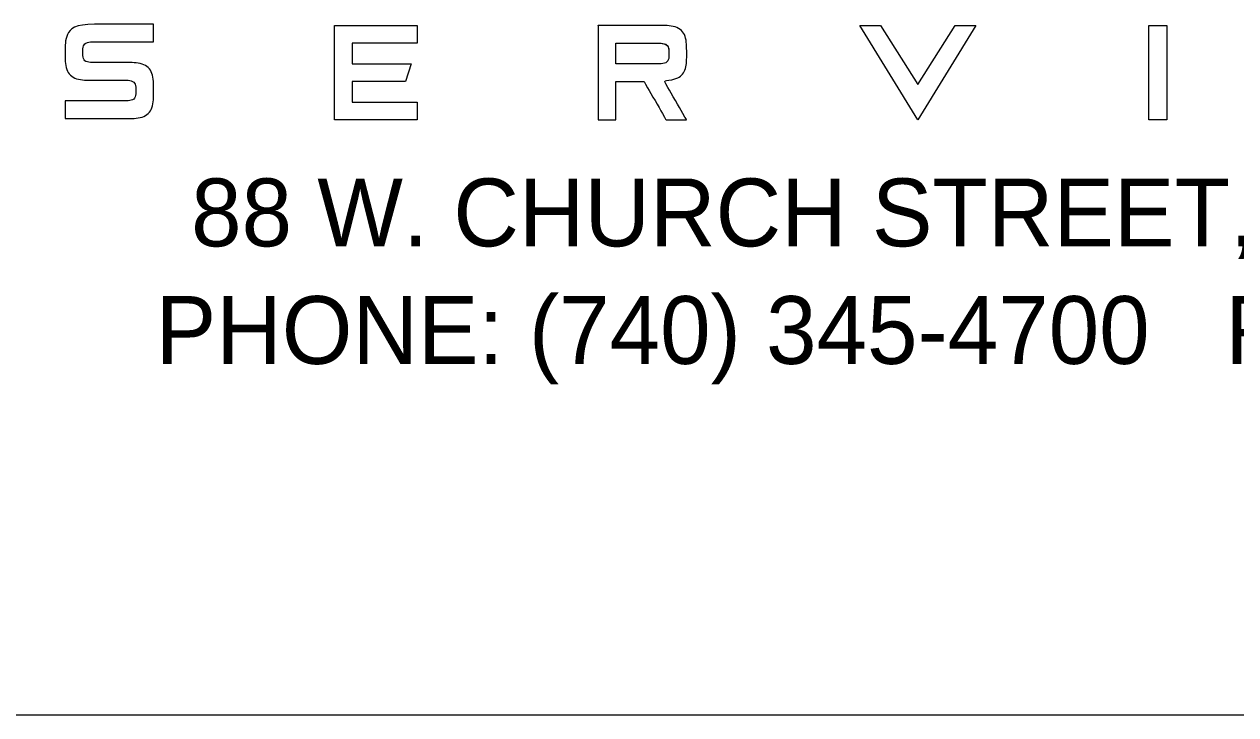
# Model space of a CAD drawing. Extents: x -50 to 112, y -27 to 22.
# Drawn here: x 71.03 to 71.911, y 2.5 to 3.003 of the extents above; entities that cross this region are included whole.
import ezdxf

# ---------------------------------------------------------------- set-up
doc = ezdxf.new("R2010")
doc.units = 0
doc.layers.add('Default', color=7, linetype='Continuous')
doc.layers.add('SH_Border', color=7, linetype='Continuous')

msp = doc.modelspace()

# ---------------------------------------------------------------- linework, layer by layer
at = {"layer": 'Default'}
for p, q in [((71.2555, 2.93307), (71.2555, 3.00176)), ((71.2555, 3.00176), (71.3156, 3.00176)), ((71.3156, 3.00176), (71.3156, 2.98888)), ((71.67986, 2.93307), (71.63775, 3.00176)), ((71.63775, 3.00176), (71.6526, 3.00176)), ((71.6526, 3.00176), (71.67986, 2.95883)), ((71.67986, 2.95883), (71.70713, 3.00176)), ((71.72198, 3.00176), (71.67986, 2.93307)), ((71.70713, 3.00176), (71.72198, 3.00176)), ((71.84804, 2.93307), (71.84804, 3.00176)), ((71.84804, 3.00176), (71.86092, 3.00176)), ((71.86092, 3.00176), (71.86092, 2.93307)), ((71.3156, 2.98888), (71.26838, 2.98888)), ((71.26838, 2.98888), (71.26838, 2.97385)), ((71.26838, 2.97385), (71.31131, 2.97385)), ((71.31131, 2.97385), (71.30702, 2.96097)), ((71.30702, 2.96097), (71.26838, 2.96097)), ((71.26838, 2.96097), (71.26838, 2.94595)), ((71.26838, 2.94595), (71.3156, 2.94595)), ((71.3156, 2.94595), (71.3156, 2.93307)), ((71.3156, 2.93307), (71.2555, 2.93307)), ((71.86092, 2.93307), (71.84804, 2.93307))]:
    msp.add_line(p, q, dxfattribs=at)
for points in [[(71.26838, 2.94595), (71.3156, 2.94595), (71.3156, 2.93307), (71.2555, 2.93307), (71.2555, 3.00176), (71.3156, 3.00176), (71.3156, 2.98888), (71.26838, 2.98888), (71.26838, 2.97385), (71.31131, 2.97385), (71.30702, 2.96097), (71.26838, 2.96097), (71.26838, 2.94595)], [(71.6526, 3.00176), (71.67986, 2.95883), (71.70713, 3.00176), (71.72198, 3.00176), (71.67986, 2.93307), (71.63775, 3.00176), (71.6526, 3.00176)], [(71.86092, 2.93307), (71.84804, 2.93307), (71.84804, 3.00176), (71.86092, 3.00176), (71.86092, 2.93307)]]:
    msp.add_lwpolyline(points, dxfattribs=at)
for points, degree in [([(71.08088, 3.00265), (71.08088, 3.00265), (71.12381, 3.00265), (71.12381, 3.00265), (71.12381, 3.00265), (71.12381, 2.98977), (71.12381, 2.98977), (71.12381, 2.98977), (71.08088, 2.98977), (71.08088, 2.98977), (71.07515, 2.98977), (71.07229, 2.98726), (71.07229, 2.98225), (71.07229, 2.97724), (71.07515, 2.97474), (71.08088, 2.97474), (71.08088, 2.97474), (71.10235, 2.97474), (71.10235, 2.97474), (71.11666, 2.97474), (71.12381, 2.96794), (71.12381, 2.95435), (71.12381, 2.94075), (71.11666, 2.93395), (71.10235, 2.93395), (71.10235, 2.93395), (71.05941, 2.93395), (71.05941, 2.93395), (71.05941, 2.93395), (71.05941, 2.94683), (71.05941, 2.94683), (71.05941, 2.94683), (71.10235, 2.94683), (71.10235, 2.94683), (71.10807, 2.94683), (71.11093, 2.94934), (71.11093, 2.95435), (71.11093, 2.95936), (71.10807, 2.96186), (71.10235, 2.96186), (71.10235, 2.96186), (71.08088, 2.96186), (71.08088, 2.96186), (71.06657, 2.96186), (71.05941, 2.96866), (71.05941, 2.98225), (71.05941, 2.99585), (71.06657, 3.00265), (71.08088, 3.00265)], 3), ([(71.08088, 3.00265), (71.08088, 3.00265), (71.12381, 3.00265), (71.12381, 3.00265), (71.12381, 3.00265), (71.12381, 2.98977), (71.12381, 2.98977), (71.12381, 2.98977), (71.08088, 2.98977), (71.08088, 2.98977), (71.07515, 2.98977), (71.07229, 2.98726), (71.07229, 2.98225), (71.07229, 2.97724), (71.07515, 2.97474), (71.08088, 2.97474), (71.08088, 2.97474), (71.10235, 2.97474), (71.10235, 2.97474), (71.11666, 2.97474), (71.12381, 2.96794), (71.12381, 2.95435), (71.12381, 2.94075), (71.11666, 2.93395), (71.10235, 2.93395), (71.10235, 2.93395), (71.05941, 2.93395), (71.05941, 2.93395), (71.05941, 2.93395), (71.05941, 2.94683), (71.05941, 2.94683), (71.05941, 2.94683), (71.10235, 2.94683), (71.10235, 2.94683), (71.10807, 2.94683), (71.11093, 2.94934), (71.11093, 2.95435), (71.11093, 2.95936), (71.10807, 2.96186), (71.10235, 2.96186), (71.10235, 2.96186), (71.08088, 2.96186), (71.08088, 2.96186), (71.06657, 2.96186), (71.05941, 2.96866), (71.05941, 2.98225), (71.05941, 2.99585), (71.06657, 3.00265), (71.08088, 3.00265)], 3), ([(71.44729, 3.00176), (71.44729, 3.00176), (71.44729, 2.93307), (71.44729, 2.93307)], 2), ([(71.44729, 2.93307), (71.44729, 2.93307), (71.46017, 2.93307), (71.46017, 2.93307), (71.46017, 2.93307), (71.46017, 2.96097), (71.46017, 2.96097), (71.46017, 2.96097), (71.4806, 2.96097), (71.4806, 2.96097), (71.4806, 2.96097), (71.4967, 2.93307), (71.4967, 2.93307), (71.4967, 2.93307), (71.5116, 2.93307), (71.5116, 2.93307), (71.5116, 2.93307), (71.49529, 2.96132), (71.49529, 2.96132), (71.50622, 2.9628), (71.51169, 2.96949), (71.51169, 2.98137), (71.51169, 2.99496), (71.50453, 3.00176), (71.49022, 3.00176), (71.49022, 3.00176), (71.44729, 3.00176), (71.44729, 3.00176)], 3), ([(71.44729, 3.00176), (71.44729, 3.00176), (71.49022, 3.00176), (71.49022, 3.00176), (71.50453, 3.00176), (71.51169, 2.99496), (71.51169, 2.98137), (71.51169, 2.96949), (71.50622, 2.9628), (71.49529, 2.96132), (71.49529, 2.96132), (71.5116, 2.93307), (71.5116, 2.93307), (71.5116, 2.93307), (71.4967, 2.93307), (71.4967, 2.93307), (71.4967, 2.93307), (71.4806, 2.96097), (71.4806, 2.96097), (71.4806, 2.96097), (71.46017, 2.96097), (71.46017, 2.96097), (71.46017, 2.96097), (71.46017, 2.93307), (71.46017, 2.93307), (71.46017, 2.93307), (71.44729, 2.93307), (71.44729, 2.93307), (71.44729, 2.93307), (71.44729, 3.00176), (71.44729, 3.00176)], 3), ([(71.46017, 2.98888), (71.46017, 2.98888), (71.49022, 2.98888), (71.49022, 2.98888)], 2), ([(71.49022, 2.98888), (71.49594, 2.98888), (71.49881, 2.98637), (71.49881, 2.98137), (71.49881, 2.97636), (71.49594, 2.97385), (71.49022, 2.97385), (71.49022, 2.97385), (71.46017, 2.97385), (71.46017, 2.97385), (71.46017, 2.97385), (71.46017, 2.98888), (71.46017, 2.98888)], 3), ([(71.46017, 2.98888), (71.46017, 2.98888), (71.46017, 2.97385), (71.46017, 2.97385), (71.46017, 2.97385), (71.49022, 2.97385), (71.49022, 2.97385), (71.49594, 2.97385), (71.49881, 2.97636), (71.49881, 2.98137), (71.49881, 2.98637), (71.49594, 2.98888), (71.49022, 2.98888), (71.49022, 2.98888), (71.46017, 2.98888), (71.46017, 2.98888)], 3)]:
    msp.add_open_spline(points, degree=degree, dxfattribs=at)
at = {"layer": 'SH_Border'}
msp.add_line((71, 2.5), (72.5, 2.5), dxfattribs=at)

# ---------------------------------------------------------------- texts
at = {"layer": 'Default'}
for s, p in [('88 W. CHURCH STREET, NEWARK, OHIO 43055', (71.1511, 2.84096)), ('PHONE: (740) 345-4700   FAX: (740) 522-4706', (71.12537, 2.75537))]:
    msp.add_text(s, height=0.0493871, dxfattribs=at).set_placement(p)

doc.saveas('drawing.dxf')
